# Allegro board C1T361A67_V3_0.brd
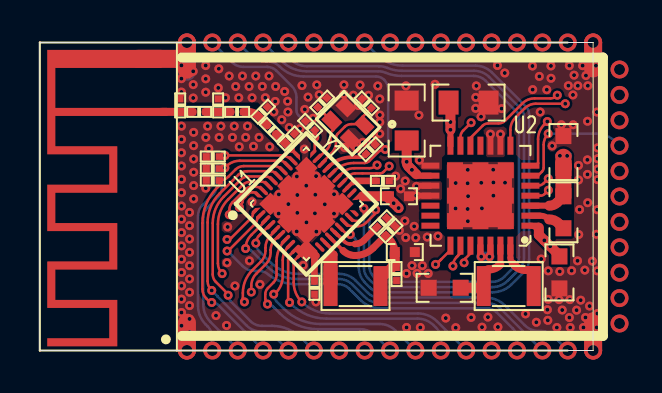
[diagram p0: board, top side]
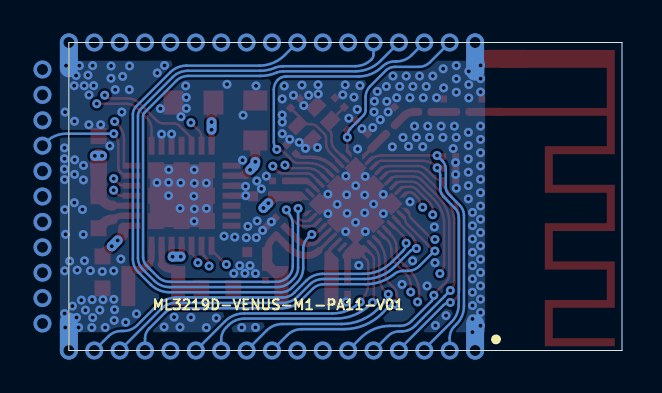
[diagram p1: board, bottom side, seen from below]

Outline 27.67 x 15.4 mm; copper layers: TOP, GND, POWER, BOTTOM. Coordinates in mm from the lower left corner of the outline.
Outline path: 0,15.4 27.67,15.4 27.67,0 26.4,0 0,0 0,15.4

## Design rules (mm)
constraint set DEFAULT: min track width 0.127, pair gap 0.1

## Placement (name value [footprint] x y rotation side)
C1  0R  [0201]  7.96 11.93 180 top
C2  NC  [0201]  11.15 11.94 45 top
C3  NC  [0201]  8.91 12.25 90 top
C4  NC  [0201]  7.01 12.25 270 top
C5  1uF  [0201]  13.51 11.24 315 top
C6  1uF  [0201]  16.54 10.06 45 top
C7  10uF  [0402]  17.95 7.71 0 top
C8  1uF  [0201]  17.15 8.48 0 top
C10  NC  [0201]  14.12 12.4 45 top
C11  NC  [0201]  16.35 12.35 315 top
C12  2.2uF  [0201]  13.73 3.14 90 top
C13  1uF  [0201]  17.1 6.41 45 top
C14  2.2uF  [0201]  17.83 3.82 270 top
C16  10uF  [0603C]  26.19 9.92 90 top
C17  100uF  [0805C]  18.34 11.5 270 top
C18  10uF  [0805C]  21.44 12.4 180 top
C19  10uF  [0603C]  20.24 3.14 180 top
C20  22uF  [0603C]  25.99 3.91 270 top
C21  NC/3.9pF  [0201]  8.64 8.5 0 top
C22  NC/3.9pF  [0201]  8.64 9.1 0 top
C23  NC/3.9pF  [0201]  8.64 9.7 180 top
C24  10uF  [0402]  18.25 4.92 0 top
C25  0.1uF  [0201]  17.53 5.99 45 top
D1  TT0321SB/NC  [0201]  12.49 10.6 225 top
L1  220pF  [0201]  11.59 11.04 135 top
L2  0R  [0201]  9.86 11.93 180 top
L3  6.8uH  [1008L]  15.78 3.22 180 top
L5  10uH  [0603L]  26.18 6.91 270 top
L6  10uH  [1008L]  23.45 3.22 180 top
U1  TL3219D  [QFN_4X4_38PIN_0P35_2P9X2P9]  13.32 7.33 45 top
U2  AEM10941  [QFN_5X5_28PIN_0P5_3P15X3P15]  22.03 7.74 180 top
U3  MODULE_15p4mm  [MODULE_BUTEO_EH_1107]  15.61 8.97 0 top
Y1  24MHz-12pF-+/-10ppm  [OSCCC160X200X065]  15.45 11.41 135 top

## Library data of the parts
C1-C4 C10 C11 = C1608_NC: User Part Number: pn; Tolerance: RichardLC
C5 C6 C8 C12-C14 C21-C23 C25 = C1005X5R1C104K: User Part Number: pn; Tolerance: RichardLC
C7 C16-C20 C24 = C1005X5R1C104K
D1 = DIODE SCHOTTKY_0: User Part Number: pn; Tolerance: RichardLC
L1 L2 L6 = MLK1608_000R: User Part Number: pn; Tolerance: RichardLC
L3 = IND_0: User Part Number: pn; Tolerance: RichardLC
L5 = MLK1608_000R
U1 = TL3219D: Tolerance: RichardLC
U2 = TLSR9517C_3
U3 = TLSR8868ET48_12: User Part Number: PN
Y1 = CRYSTAL4/SM_0

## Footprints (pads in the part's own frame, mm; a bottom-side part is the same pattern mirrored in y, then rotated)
0201
  rect 0.35x0.33 smd: 1(-0.325,0) 2(0.325,0)
0402
  rect 0.5x0.5 smd: 1(-0.5,0) 2(0.5,0)
0603C
  rect 0.8x0.8 smd: 1(-0.8,0) 2(0.8,0)
0603L
  rect 0.8x0.8 smd: 1(-0.8,0) 2(0.8,0)
0805C
  rect 1x1.2 smd: 1(-1,0) 2(1,0)
1008L
  rect 0.7x2 smd: 1(-1.25,0) 2(1.25,0)
MODULE_BUTEO_EH_1107
  rect 0.25x0.25 smd: 1(-8.255,-8.97) 2(-6.985,-8.97) 3(-5.715,-8.97) 4(-4.445,-8.97) 5(-3.175,-8.97) 6(-1.905,-8.97) 7(-0.635,-8.97) 8(0.635,-8.97) 9(1.905,-8.97) 10(3.175,-8.97) 11(4.445,-8.97) 12(5.715,-8.97) 13(6.985,-8.97) 14(8.255,-8.97) 15(9.525,-8.97) 16(10.795,-8.97) 17(12.065,-8.97) 18(13.385,-7.62) 19(13.385,-6.35) 20(13.385,-5.08) 21(13.385,-3.81) 22(13.385,-2.54) 23(13.385,-1.27) 24(13.385,0) 25(13.385,1.27) 26(13.385,2.54) 27(13.385,3.81) 28(13.385,5.08) 29(12.065,6.43) 30(10.795,6.43) 31(9.525,6.43) 32(8.255,6.43) 33(6.985,6.43) 34(5.715,6.43) 35(4.445,6.43) 36(3.175,6.43) 37(1.905,6.43) 38(0.635,6.43) 39(-0.635,6.43) 40(-1.905,6.43) 41(-3.175,6.43) 42(-4.445,6.43) 43(-5.715,6.43) 44(-6.985,6.43) 45(-8.255,6.43)
  rect 0.8x0.8 smd rot 45: 46(-2.281,0.155) 47(-3.179,-0.744) 48(-4.077,-1.641) 49(-1.383,-0.744) 50(-2.281,-1.641) 51(-3.179,-2.539) 52(-0.485,-1.641) 53(-1.383,-2.539)
  custom 0.2x0.2 smd rot 45: 54(-2.281,-4.003)
  rect 0.8x0.8 smd: 55(5.157,0.041) 56(6.427,0.041) 57(7.697,0.041) 58(5.157,-1.229) 59(6.427,-1.229) 60(7.697,-1.229) 61(5.157,-2.499) 62(6.427,-2.499) 63(7.697,-2.499)
OSCCC160X200X065
  rect 0.85x0.6 smd: 1(-0.65,-0.45) 4(-0.65,0.55)
  rect 0.85x0.65 smd: 2(0.65,-0.45) 3(0.65,0.55)
QFN_4X4_38PIN_0P35_2P9X2P9
  custom 0.045x0.045 smd: 1(-2,1.575) 10(-2,-1.575) 11(-1.4,-2) 19(1.4,-2) 20(2,-1.575) 29(2,1.575) 30(1.4,2) 38(-1.4,2)
  oval 0.6x0.18 smd: 2(-2,1.225) 3(-2,0.875) 4(-2,0.525) 5(-2,0.175) 6(-2,-0.175) 7(-2,-0.525) 8(-2,-0.875) 9(-2,-1.225) 21(2,-1.225) 22(2,-0.875) 23(2,-0.525) 24(2,-0.175) 25(2,0.175) 26(2,0.525) 27(2,0.875) 28(2,1.225)
  oval 0.18x0.6 smd: 12(-1.05,-2) 13(-0.7,-2) 14(-0.35,-2) 15(0,-2) 16(0.35,-2) 17(0.7,-2) 18(1.05,-2) 31(1.05,2) 32(0.7,2) 33(0.35,2) 34(0,2) 35(-0.35,2) 36(-0.7,2) 37(-1.05,2)
  custom 0.725x0.725 smd: 39(0,0)
QFN_5X5_28PIN_0P5_3P15X3P15
  rect 0.9x0.3 smd: 1(-2.5,1.5) 2(-2.5,1) 3(-2.5,0.5) 4(-2.5,0) 5(-2.5,-0.5) 6(-2.5,-1) 7(-2.5,-1.5) 15(2.5,-1.5) 16(2.5,-1) 17(2.5,-0.5) 18(2.5,0) 19(2.5,0.5) 20(2.5,1) 21(2.5,1.5)
  rect 0.3x0.9 smd: 8(-1.5,-2.5) 9(-1,-2.5) 10(-0.5,-2.5) 11(0,-2.5) 12(0.5,-2.5) 13(1,-2.5) 14(1.5,-2.5) 22(1.5,2.5) 23(1,2.5) 24(0.5,2.5) 25(0,2.5) 26(-0.5,2.5) 27(-1,2.5) 28(-1.5,2.5)
  rect 3.15x3.15 smd: 29(0,0)

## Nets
GND: C1.2 C2.2 C3.2 C4.1 C4.2 C5.1 C6.2 C7.2 C8.2 C10.2 C11.1 C12.1 C13.2 C14.2 C16.2 C17.1 C18.1 C19.2 C20.2 C21.1 C22.1 C23.2 C24.2 C25.2 D1.1 U1.39 U2.9 U2.10 U2.15 U2.17 U2.18 U2.29 U3.1 U3.17 U3.29 U3.45 U3.46 U3.47 U3.48 U3.49 U3.50 U3.51 U3.52 U3.53 U3.54 U3.55 U3.56 U3.57 U3.58 U3.59 U3.60 U3.61 U3.62 U3.63 Y1.2 Y1.4
AEM_BATT: C17.2 U2.16 U3.37
AEM_BOOST: C20.1 U2.1 U3.21
AEM_BUCK: C16.1 L5.1 U2.3 U3.26
AEM_CFG0: U2.6 U3.25
AEM_CFG1: U2.5 U3.24
AEM_CFG2: U2.4 U3.23
AEM_CHRDY: U2.23 U3.19
AEM_ENHV: U2.12 U3.30
AEM_FBHV: U2.13 U3.34
AEM_HVOUT: C18.2 U2.14 U3.35
AEM_OVCH: U2.22 U3.18
AEM_OVDIS: U2.24 U3.20
AEM_SELMPP0: U2.8 U3.28
AEM_SELMPP1: U2.7 U3.27
AEM_SRC: U2.25 U2.26 U3.22
TL_ANT: D1.2(CATHODE) L1.1 U1.30
TL_AVDD1P25: C14.1 C24.1 C25.1 L3.1 U1.14
TL_AVDD3: C8.1 U1.22
TL_PA0: U1.37 U3.32
TL_PA1: U1.7 U3.9(PIN9)
TL_PA2: U1.8 U3.10
TL_PA3: U1.10 U3.12
TL_PA4: U1.9 U3.11
TL_PA5_DM: U1.6 U3.8
TL_PA6_DP: U1.5 U3.7
TL_PA7_SWS: U1.36 U3.13
TL_PB0: U1.1 U3.31
TL_PB1: U1.38 U3.33
TL_PB5: U1.18 U3.41
TL_PB6: U1.17 U3.42
TL_PB7: U1.16 U3.38
TL_PC0_AMICP: U1.23 U3.40
TL_PC1_AMICN: U1.24 U3.39
TL_PC2: U1.25 U3.43
TL_PD1: U1.2 U3.14
TL_PD4: U1.3 U3.15
TL_PD6: U1.4 U3.16
TL_PE2: C21.2 U1.33 U3.4
TL_PE4: C23.1 U1.31 U3.2
TL_PE5: C22.2 U1.32 U3.3
TL_PE6: U1.35 U3.6
TL_PE7: U1.34 U3.5
TL_RESET: C5.2 U1.29 U3.44
TL_VBAT: C7.1 U1.20 U3.36
TL_XC1: C10.1 U1.28 Y1.3
TL_XC2: C11.2 U1.27(XC2) Y1.1
N20473879: C2.1 L1.2 L2.1
N20475567: C19.1 L6.2 U2.27
N20475608: L6.1 U2.28
N20475681: L5.2 U2.2(SWBUCK)
N20493055: C1.1 C3.1 L2.2
N20502827: C6.1 U1.26
N20503268: C12.2 U1.11
N20503276: C13.1 U1.15
N20503917: L3.2 U1.13

Pads without a net: U1 12 19 21; U2 11 19 20 21

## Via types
v1: diameter 0.45, hole 0.2, TOP to BOTTOM, 286 vias
v2: diameter 0.9, hole 0.55, TOP to BOTTOM, 45 vias

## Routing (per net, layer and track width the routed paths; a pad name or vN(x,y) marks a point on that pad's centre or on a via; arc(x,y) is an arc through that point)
GND: length 29.8
  TOP w0.127: U2.10 v1(22.53,10.82) ; C18.1 22.06,12.4 v1(21.8,12.66) ; U2.9 v1(23.03,10.82)
  TOP w0.3: U2.18 v1(18.82,7.74) ; 18.98,8.24 U2.17
  TOP w0.4: 6.07,11.93 C4.2 C1.2
  TOP w0.9: v2(7.35,0) 7.35,1.39 ; 4.88,14.58 7.33,14.58 ; v2(27.67,15.4) 27.67,14.11 ; 27.67,1.46 v2(27.67,0) ; v2(7.35,15.4) 7.35,14.04
  GND w0.9: 27.67,13.99 v2(27.67,15.4) ; v2(7.35,0) 7.35,1.37 ; v2(7.35,15.4) 7.35,13.93 ; 27.67,1.77 v2(27.67,0)
  POWER w0.9: v2(7.35,15.4) 7.35,14.12 ; v2(7.35,0) 7.35,1.47 ; v2(27.67,15.4) 27.67,14.03 ; 27.67,1.47 v2(27.67,0)
  BOTTOM w0.9: v2(27.67,15.4) 27.67,14.11 ; v2(7.35,15.4) 7.35,13.94 ; v2(7.35,0) 7.35,1.34 ; v2(27.67,0) 27.67,1.44
  vias: v1(7.07,14.26) v1(7.07,13.59) v1(7.07,12.92) v1(7.08,11.22) v1(7.08,10.56) v1(7.08,9.89) v1(7.08,9.23) v1(7.08,8.56) v1(7.08,7.89) v1(7.08,7.23) v1(7.08,6.56) v1(7.08,5.9) v1(7.08,5.23) v1(7.08,4.56) v1(7.08,3.9) v1(7.08,3.23) v1(7.08,2.57) v1(7.08,1.9) v1(7.08,1.24) v1(7.48,6.9) v1(7.48,6.24) v1(7.48,5.57) v1(7.48,4.91) v1(7.48,4.24) v1(7.48,3.58) v1(7.48,2.91) v1(7.48,2.25) v1(7.48,1.58) v1(7.48,0.92) v1(7.67,13.96) v1(7.67,13.29) v1(7.67,12.63) v1(7.69,10.91) v1(7.69,10.24) v1(7.69,9.57) v1(7.69,8.91) v1(7.69,8.25) v1(7.69,7.58) v1(8.29,14.25) v1(8.29,13.58) v1(8.29,12.91) v1(8.3,10.65) v1(8.29,8.12) v1(8.39,11.22) v1(8.33,9.4) v1(8.32,8.8) v1(8.45,10.1) v1(8.8,1.75) v1(8.95,14.09) v1(8.92,13.13) v1(8.96,10.65) v1(9.05,11.22) v1(9.28,12.64) v1(9.39,6.18) v1(9.36,4.39) v1(9.33,1.25) v1(9.46,13.72) v1(9.63,10.66) v1(9.79,13.2) v1(9.72,11.22) v1(9.75,3.23) v1(9.94,12.64) v1(9.97,10.19) v1(10.13,13.72) v1(10.29,10.66) v1(10.38,11.22) v1(10.46,13.2) v1(10.48,4.49) v1(10.61,12.64) v1(10.68,10.21) v1(10.61,7.44) v1(10.8,13.72) v1(10.96,10.66) v1(11,3.31) v1(11.12,13.2) v1(11.27,12.64) v1(11.46,13.72) v1(11.49,10.18) v1(11.79,13.2) v1(11.77,12.45) v1(11.7,11.93) v1(11.95,7.8) v1(11.94,6.85) v1(12.09,11.54) v1(12.24,12.95) v1(12.39,12.46) v1(12.4,11.93) v1(12.47,11.15) v1(12.43,7.32) v1(12.85,8.7) v1(12.87,7.77) v1(12.87,6.88) v1(12.84,5.95) v1(13.01,11.09) v1(13.11,13.25) v1(13.17,4.26) v1(13.25,12.06) v1(13.23,10.07) v1(13.32,8.24) v1(13.33,6.41) v1(13.41,12.67) v1(13.66,11.61) v1(13.77,7.79) v1(13.75,6.86) v1(13.85,13.28) v1(13.81,8.72) v1(13.82,5.95) v1(13.8,2.43) v1(13.97,12.79) v1(14.25,7.31) v1(14.71,7.81) v1(14.71,6.84) v1(15.2,12.82) v1(15.21,13.29) v1(15.24,10.15) v1(15.67,12.77) v1(15.84,10.11) v1(15.92,12.25) v1(16.01,13.27) v1(16.15,10.41) v1(16.44,12.76) v1(16.62,10.56) v1(16.9,13.23) v1(17,12.58) v1(17,11.42) v1(17,10.84) v1(17,11.78) v1(17.54,6.44) v1(17.79,8.72) v1(17.98,6) v1(18.04,8.08) v1(18.27,8.48) v1(18.25,6.48) v1(18.3,5.64) v1(18.31,13.23) v1(18.34,3.85) v1(18.34,1.15) v1(18.61,4.25) v1(18.72,6.21) v1(18.8,5.64) v1(18.83,8.21) v1(18.86,3.86) v1(18.96,11.76) v1(18.98,9.52) v1(19.02,1.15) v1(19.12,4.24) v1(19.37,5.67) v1(19.42,3.85) v1(19.76,13.31) v1(19.91,5.72) v1(20.3,1.62) v1(20.8,8.37) v1(20.79,7.1) v1(20.8,1.14) v1(21.4,9.03) v1(21.39,8.36) v1(21.39,7.08) v1(21.41,7.71) v1(21.4,6.46) v1(21.57,1.65) v1(21.8,12.11) v1(21.83,13.23) v1(22.06,11.69) v1(22.07,8.38) v1(22.11,7.11) v1(22.11,1.17) v1(22.41,1.67) v1(22.67,9.04) v1(22.68,8.4) v1(22.68,7.74) v1(22.88,14.25) v1(22.91,1.18) v1(23.09,12.09) v1(23.25,13.88) v1(23.26,8.39) v1(24.29,1.83) v1(24.64,14.22) v1(24.65,13.04) v1(24.83,1.41) v1(24.98,13.7) v1(25.02,11.92) v1(25.07,4.57) v1(25.35,13.04) v1(25.38,2.04) v1(25.42,3.98) v1(25.42,2.56) v1(25.4,1.51) v1(25.56,14.23) v1(25.56,13.61) v1(25.62,10.23) v1(25.86,1.15) v1(25.96,2.54) v1(26.08,11.29) v1(26,3.95) v1(26.12,2.02) v1(26.48,14.24) v1(26.43,13.24) v1(26.48,1.65) v1(26.59,3.99) v1(26.51,2.54) v1(26.52,1.15) v1(26.66,12.78) v1(26.67,11.29) v1(26.72,13.77) v1(26.89,4.48) v1(26.84,2.02) v1(26.91,13.24) v1(26.94,9.25) v1(26.94,8.53) v1(26.99,7.05) v1(26.95,5.8) v1(27.05,2.52) v1(27.14,14.24) v1(27.19,1.15) v1(27.25,4.02) v1(27.29,1.65) v1(27.31,13.75) v1(27.39,11.46) v1(27.38,9.53) v1(27.39,8.81) v1(27.4,7.39) v1(27.41,13.24) v1(27.49,2.22) v1(27.63,4.47) v1(27.81,14.24) v1(27.86,11.92) v1(27.89,10.13) v1(27.89,9.59) v1(27.89,9.07) v1(27.89,8.54) v1(27.87,7.04) v1(27.84,5.81) v1(27.88,3.98) v1(27.89,1.85) v1(27.85,1.15)
AEM_BATT: length 9.8
  TOP w0.3: U2.16 19,8.74 arc(18.9,8.76) 18.82,8.81
  TOP w0.5: 18.82,8.81 v1(18.61,9.03) 18.44,9.19 arc(18.37,9.3) v1(18.34,9.44) C17.2
  POWER w0.5: v1(18.61,9.03) 18.44,9.19 arc(18.37,9.3) v1(18.34,9.44) arc(18.34,9.44) 18.34,9.45 18.34,11.85 arc(18.26,12.22) 18.06,12.52 18.06,12.52 arc(17.65,13.13) 17.51,13.85 v2(17.51,15.4)
  BOTTOM w0.5: v1(18.61,9.03) 18.44,9.19 arc(18.37,9.3) v1(18.34,9.44)
AEM_BOOST: length 7
  TOP w0.127: U2.1 24.86,6.24 24.96,6.14
  TOP w0.3: 24.89,6.09 arc(24.72,6.2) U2.1
  TOP w0.5: 24.96,6.14 24.96,5.78 v1(25.23,5.5) 25.23,5.5 v1(25.52,5.21) 25.99,4.75 C20.1
  POWER w0.5: v2(28.99,5.16) 25.65,5.16 arc(25.58,5.17) v1(25.52,5.21) arc(25.52,5.21) 25.52,5.22 v1(25.23,5.5)
  BOTTOM w0.5: v1(25.23,5.5) 25.52,5.22 arc(25.52,5.21) v1(25.52,5.21)
AEM_BUCK: length 8.8
  TOP w0.127: 26.19,9.29 arc(26.23,9.53) v1(26.37,9.73) ; v1(26.01,9.74) arc(26.14,9.54) 26.19,9.31
  TOP w0.3: U2.3 25.48,7.24
  TOP w0.5: L5.1 26.18,7.71 25.87,7.4 arc(25.69,7.28) 25.48,7.24
  TOP w0.8: L5.1 26.18,9.12 arc(26.18,9.12) C16.1 26.19,9.69
  POWER w0.5: v1(26.01,9.74) 26.36,9.74 v1(26.37,9.73) arc(26.62,9.78) 26.83,9.92 28.05,11.14 arc(28.24,11.27) 28.46,11.31 28.51,11.31 arc(28.77,11.36) v2(28.99,11.51)
  BOTTOM w0.5: v1(26.01,9.74) 26.36,9.74 arc(26.36,9.74) v1(26.37,9.73)
AEM_CFG0: length 6.6
  TOP w0.127: U2.6 24.91,8.74 25.11,8.94 arc(25.17,9.03) 25.19,9.15 25.19,10.29 arc(25.25,10.59) v1(25.42,10.84)
  BOTTOM w0.127: v1(25.42,10.84) 27.82,10.84 arc(28.35,10.73) 28.8,10.43 v2(28.99,10.24) 28.86,10.37
AEM_CFG1: length 5.1
  TOP w0.127: U2.5 24.9,8.24 arc(25.06,8.27) 25.2,8.37 v1(25.43,8.59)
  POWER w0.127: v2(28.99,8.97) 28.35,8.33 arc(28.08,8.15) 27.77,8.09 26.38,8.09 arc(26.05,8.15) 25.78,8.34 25.6,8.52 arc(25.52,8.57) v1(25.43,8.59)
AEM_CFG2: length 4.6
  TOP w0.127: v1(25.43,8.01) 25.24,7.82 arc(25.15,7.76) 25.04,7.74 U2.4
  POWER w0.127: v2(28.99,7.7) arc(28.85,7.79) 28.69,7.82 25.89,7.82 arc(25.64,7.87) v1(25.43,8.01)
AEM_CHRDY: length 10.2
  TOP w0.127: U2.23 21.03,4.86 20.91,4.73 ; 20.91,4.73 20.87,4.7 ; 20.91,4.73 20.84,4.67 arc(20.7,4.46) v1(20.66,4.22) 20.66,4.26
  POWER w0.127: v2(28.99,2.62) 28.56,3.05 arc(28.35,3.19) 28.11,3.24 22.23,3.24 arc(21.56,3.37) 21,3.75 20.75,3.99 arc(20.68,4.1) v1(20.66,4.22)
AEM_ENHV: length 8.3
  TOP w0.127: v1(25.88,12.77) 25.84,12.73 arc(25.7,12.64) 25.54,12.61 24.74,12.61 arc(24.41,12.54) 24.13,12.35 23.27,11.49 arc(23.12,11.39) 22.94,11.35 22.42,11.35 arc(22.27,11.33) 22.14,11.24 21.53,10.63 U2.12
  POWER w0.127: v2(26.4,15.4) 26.08,15.08 arc(26.01,14.98) 25.99,14.85 25.99,13.03 arc(25.96,12.89) v1(25.88,12.77)
AEM_FBHV: length 5.4
  TOP w0.127: U2.13 21.03,10.67 arc(21.07,10.84) 21.17,10.99 v1(21.57,11.39)
  POWER w0.127: v1(21.57,11.39) arc(21.43,11.6) 21.38,11.84 21.38,15.26 arc(21.36,15.33) v2(21.32,15.4)
AEM_HVOUT: length 7.1
  TOP w0.3: v1(20.53,11.04) U2.14
  TOP w0.5: C18.2 20.53,12.3 v1(20.53,11.42) v1(20.53,11.04)
  POWER w0.5: v1(20.53,11.04) v1(20.53,11.42) 20.53,11.42 20.53,13.22 arc(20.48,13.5) 20.32,13.75 arc(20.12,14.04) 20.05,14.39 v2(20.05,15.4) 20.05,15.4
  BOTTOM w0.5: v1(20.53,11.04) v1(20.53,11.42)
AEM_OVCH: length 11.9
  TOP w0.127: 20.06,4.55 19.83,4.32 arc(19.81,4.31) v1(19.79,4.3) ; 20.06,4.55 20.53,5.02 U2.22 ; 20.06,4.55 19.84,4.32
  POWER w0.127: v1(19.79,4.3) 19.84,4.3 arc(19.95,4.28) 20.05,4.21 20.7,3.57 arc(21.35,3.13) 22.12,2.98 26.99,2.98 arc(27.33,2.91) 27.62,2.72 v2(28.99,1.35)
AEM_OVDIS: length 9.4
  TOP w0.127: v1(21.21,4.39) 21.21,4.43 arc(21.23,4.53) 21.29,4.61 21.53,4.85 U2.24
  POWER w0.127: v2(28.99,3.89) 28.69,3.59 arc(28.59,3.53) 28.48,3.5 22.18,3.5 arc(21.8,3.58) 21.47,3.8 21.45,3.82 arc(21.28,4.08) v1(21.21,4.39)
AEM_SELMPP0: length 7.6
  TOP w0.127: U2.8 23.53,11.04 arc(23.6,11.37) 23.78,11.65 24.25,12.11 arc(24.5,12.28) 24.8,12.34 v1(26.28,12.34)
  POWER w0.127: v1(26.28,12.34) 26.93,12.34 arc(27.17,12.39) 27.38,12.52 28.85,13.99 arc(28.91,14.03) v2(28.99,14.05)
AEM_SELMPP1: length 6.7
  TOP w0.127: v1(25.38,11.45) 25.21,11.28 arc(24.99,10.96) 24.92,10.57 24.92,9.37 24.79,9.24 U2.7
  POWER w0.127: v2(28.99,12.78) 28.39,12.78 arc(28.05,12.71) 27.76,12.52 27.55,12.31 arc(27.11,12.02) 26.6,11.91 26.34,11.91 arc(25.88,11.82) 25.49,11.56 v1(25.38,11.45)
AEM_SRC: length 9.1
  TOP w0.3: v1(22.07,4.69) 22.03,4.73 U2.25 ; U2.26 22.53,4.74 v1(22.48,4.69)
  POWER w0.5: v1(22.07,4.69) 22.47,4.69 arc(22.48,4.69) v1(22.48,4.69) arc(22.7,4.73) 22.89,4.86 23.97,5.94 arc(24.52,6.3) 25.16,6.43 v2(28.99,6.43)
  BOTTOM w0.5: v1(22.07,4.69) 22.47,4.69 arc(22.48,4.69) v1(22.48,4.69)
TL_ANT: length 1.5
  TOP w0.18: 12.55,10.09 12.9,9.73 U1.30
  TOP w0.4: 12.55,10.09 D1.2 L1.1
TL_AVDD1P25: length 7.5
  TOP w0.18: U1.14 15.15,5 arc(15.16,5) 15.16,5
  TOP w0.2: C24.1 17.83,4.84 C14.1 17.6,4.15
  TOP w0.35: 15.16,5 arc(15.43,4.82) 15.76,4.75 arc(16.25,4.85) 16.67,5.13 C25.1 17.47,5.59 arc(17.68,5.28) C24.1
  TOP w0.5: L3.1 17.03,3.58 17.75,4.29 C24.1
TL_AVDD3: length 1.8
  TOP w0.18: 15.79,8.48 15.66,8.35 15.59,8.35 ; 15.59,8.35 15.72,8.49 ; 15.59,8.35 U1.22
  TOP w0.33: 15.79,8.48 C8.1
TL_PA0: length 26.1
  TOP w0.127: U1.37 11.11,8.06 arc(10.97,8.15) 10.8,8.19 10.58,8.19 arc(10.42,8.15) 10.28,8.06 9.63,7.41 arc(9.51,7.23) 9.47,7.02 v1(9.47,6.79)
  POWER w0.127: v2(23.86,15.4) 23.94,15.32 23.94,8.23 arc(23.88,7.92) 23.71,7.66 22.4,6.35 arc(20.83,5.3) 18.97,4.93 13.58,4.93 arc(12.94,5.06) 12.39,5.42 11.8,6.01 arc(11.44,6.25) 11.02,6.34 10.56,6.34 arc(9.97,6.46) v1(9.47,6.79)
TL_PA1: length 10.5
  TOP w0.127: U1.7 12.28,5.54 arc(11.95,5.05) 11.83,4.46 11.83,3.76 arc(11.79,3.57) 11.69,3.41 11.4,3.12 arc(11.3,2.98) 11.27,2.81 11.27,2.59 arc(11.3,2.44) v1(11.38,2.32)
  BOTTOM w0.127: v2(17.51,0) 16.74,0.77 arc(16.41,0.99) 16.02,1.07 13.91,1.07 arc(12.87,1.27) 12,1.86 11.65,2.21 arc(11.52,2.29) v1(11.38,2.32)
TL_PA2: length 11
  TOP w0.127: U1.8 12.42,5.19 arc(12.22,4.88) 12.14,4.52 12.14,3.72 arc(12.05,3.27) 11.8,2.89 11.73,2.82 v1(11.69,2.82)
  BOTTOM w0.127: v2(18.78,0) 17.78,1 arc(17.42,1.24) 16.99,1.32 14.03,1.32 arc(13.04,1.52) 12.21,2.08 11.85,2.44 arc(11.73,2.61) v1(11.69,2.82)
TL_PA3: length 11.7
  TOP w0.127: 13.07,2.46 v1(13.1,2.43) arc(12.8,2.88) 12.69,3.41 12.69,4.31 arc(12.72,4.46) 12.8,4.58 U1.10
  BOTTOM w0.127: v2(21.32,0) 19.87,1.45 arc(19.42,1.75) 18.9,1.85 14.49,1.85 arc(13.73,2) v1(13.1,2.43)
TL_PA4: length 11.7
  TOP w0.127: U1.9 12.52,4.79 arc(12.44,4.67) 12.41,4.53 12.41,2.58 arc(12.43,2.48) v1(12.48,2.4)
  BOTTOM w0.127: v1(12.48,2.4) 12.57,2.32 arc(13.37,1.78) 14.32,1.6 18.88,1.6 arc(19.32,1.51) 19.69,1.26 19.8,1.15 arc(19.99,0.87) 20.05,0.55 v2(20.05,0)
TL_PA5_DM: length 10.5
  TOP w0.127: U1.6 12,5.79 11.76,5.56 arc(11.6,5.31) 11.54,5.02 11.54,4.91 arc(11.47,4.58) 11.29,4.31 10.82,3.84 arc(10.64,3.56) 10.57,3.23 v1(10.57,2.92)
  POWER w0.127: v2(16.24,0) 15.49,0.75 arc(14.55,1.38) 13.45,1.6 11.46,1.6 arc(11.12,1.66) 10.83,1.85 arc(10.71,2.03) 10.67,2.24 10.67,2.67 arc(10.65,2.81) v1(10.57,2.92)
TL_PA6_DP: length 10.3
  TOP w0.127: U1.5 11.79,6 11.54,5.75 arc(11.35,5.47) 11.28,5.13 11.28,4.99 arc(11.22,4.7) 11.06,4.45 10.62,4.01 arc(10.27,3.49) 10.15,2.88 10.15,2.62 arc(10.17,2.52) v1(10.23,2.43)
  POWER w0.127: v2(14.97,0) 14.97,0.52 arc(14.94,0.66) 14.86,0.78 arc(14.25,1.19) 13.53,1.33 11.49,1.33 arc(10.97,1.44) 10.53,1.73 10.5,1.76 arc(10.3,2.07) v1(10.23,2.43)
TL_PA7_SWS: length 21.1
  TOP w0.127: 11.42,8.25 11.33,8.33 arc(11.21,8.41) 11.07,8.44 10.55,8.44 arc(10.32,8.4) 10.13,8.27 9.41,7.55 arc(9.03,6.99) 8.9,6.32 8.9,4.35 arc(8.96,4.08) v1(9.11,3.85)
  POWER w0.127: v1(9.11,3.85) 9.12,3.84 arc(9.23,3.76) 9.36,3.74 15.86,3.74 arc(18.57,3.2) 20.87,1.66 22.53,0 v2(22.59,0)
TL_PB0: length 26.6
  TOP w0.127: U1.1 10.8,6.99 10.65,6.85 10.65,6.85 arc(10.63,6.72) 10.56,6.62 9.59,5.65 arc(9.48,5.58) v1(9.36,5.55)
  POWER w0.127: v1(9.36,5.55) 9.66,5.86 arc(9.91,6.02) 10.2,6.08 11,6.08 arc(11.35,6.01) 11.64,5.81 12.25,5.21 arc(12.84,4.81) 13.54,4.68 18.95,4.68 arc(20.98,5.08) 22.7,6.23 23.84,7.36 arc(24.11,7.77) 24.2,8.24 24.2,14.14 arc(24.25,14.39) 24.39,14.6 25.13,15.34 v2(25.13,15.4)
TL_PB1: length 24.5
  TOP w0.127: U1.38 10.82,7.85 arc(10.75,7.9) 10.67,7.91 10.61,7.91 arc(10.51,7.89) 10.42,7.83 10.4,7.82 10.29,7.7 10.21,7.63 arc(10.15,7.53) 10.12,7.41 arc(10.07,7.28) 9.98,7.17 v1(9.97,7.16)
  POWER w0.127: v2(22.59,15.4) 23.48,14.51 arc(23.63,14.29) 23.68,14.03 23.68,8.32 arc(23.63,8.04) 23.47,7.81 22.18,6.51 arc(20.72,5.54) 19,5.2 13.54,5.2 arc(13.03,5.3) 12.6,5.58 12,6.18 arc(11.55,6.49) 11.01,6.59 arc(10.58,6.68) 10.21,6.93 v1(9.97,7.16)
TL_PB5: length 34.3
  TOP w0.127: 15.48,6.66 U1.18 15.54,6.6 arc(15.68,6.5) 15.85,6.47 15.88,6.47 arc(16.02,6.5) 16.14,6.58 arc(16.19,6.65) 16.2,6.73 v1(16.2,7.1)
  BOTTOM w0.127: v2(12.43,15.4) 12.43,14.8 arc(12.46,14.67) 12.53,14.55 arc(12.91,14.3) 13.35,14.22 16.95,14.22 ; v1(16.2,7.1) 16.2,4.14 arc(16.26,3.84) 16.44,3.58 16.56,3.46 arc(16.88,3.25) 17.26,3.17 22.63,3.17 arc(23.05,3.25) 23.4,3.49 23.99,4.08 arc(24.16,4.33) 24.21,4.62 24.21,11.73 arc(24.18,11.92) 24.07,12.07 22.47,13.68 arc(22.13,13.9) 21.73,13.98 18.11,13.98 arc(17.74,14.02) 17.37,14.13 arc(17.16,14.19) 16.95,14.22 ; 16.95,14.22 16.95,14.22
TL_PB6: length 34.7
  TOP w0.127: U1.17 15.28,6.36 arc(15.44,6.25) 15.63,6.21 15.9,6.21 arc(16.12,6.26) 16.31,6.39 16.72,6.8 arc(16.78,6.88) 16.8,6.97 16.8,7.03 v1(16.79,7.03)
  BOTTOM w0.127: v2(11.16,15.4) 12.08,14.48 arc(12.66,14.09) 13.34,13.96 16.93,13.96 arc(17.12,13.94) 17.3,13.89 arc(17.68,13.77) 18.09,13.73 21.7,13.73 arc(22.02,13.66) 22.3,13.48 23.89,11.89 arc(23.94,11.81) 23.96,11.72 23.96,4.66 arc(23.91,4.44) 23.79,4.25 23.23,3.69 arc(22.95,3.5) 22.61,3.43 17.3,3.43 arc(16.98,3.5) 16.7,3.68 arc(16.53,3.94) 16.47,4.24 16.47,6.26 arc(16.54,6.65) 16.76,6.97 16.79,7 v1(16.79,7.03)
TL_PB7: length 29.4
  TOP w0.127: U1.16 15.22,5.93 arc(15.36,5.83) v1(15.52,5.8)
  BOTTOM w0.127: v2(16.24,15.4) 16.87,14.77 arc(17.45,14.38) 18.14,14.24 21.79,14.24 arc(22.23,14.15) 22.6,13.91 24.31,12.2 arc(24.43,12.02) 24.47,11.81 24.47,4.57 arc(24.4,4.22) 24.2,3.92 23.58,3.3 arc(23.15,3.01) 22.64,2.91 17.04,2.91 arc(16.76,2.97) 16.52,3.13 16.26,3.39 arc(16.03,3.74) 15.95,4.14 15.95,5.07 arc(15.89,5.38) 15.71,5.65 15.55,5.8 v1(15.52,5.8)
TL_PC0_AMICP: length 12
  TOP w0.127: U1.23 15.48,8.74 arc(15.6,8.82) 15.75,8.85 16.12,8.85 ; 16.83,8.85 17.01,8.85 arc(17.1,8.87) 17.17,8.92 v1(17.47,9.22)
  TOP w0.128: 16.12,8.85 16.83,8.85
  POWER w0.127: v2(13.7,15.4) 14.29,14.81 arc(14.44,14.58) 14.5,14.31 14.5,10.22 arc(14.58,9.81) 14.81,9.47 15.17,9.11 arc(15.45,8.92) 15.78,8.85 16.92,8.85 arc(17.09,8.89) 17.24,8.98 v1(17.47,9.22)
TL_PC1_AMICN: length 10.2
  TOP w0.127: v1(16.86,9.27) arc(16.69,9.16) 16.48,9.12 ; 15.72,9.12 arc(15.39,9.05) 15.1,8.86
  TOP w0.128: v1(16.86,9.27) 16.86,9.25 ; 15.1,8.86 U1.24 ; 16.48,9.12 15.72,9.12
  POWER w0.127: v2(14.97,15.4) 14.76,15.19 14.76,10.27 arc(14.82,9.92) 15.02,9.63 15.33,9.32 arc(15.56,9.17) 15.82,9.11 16.48,9.11 arc(16.69,9.15) v1(16.86,9.27)
TL_PC2: length 14.6
  TOP w0.127: U1.25 14.72,8.97 arc(15.17,9.27) 15.69,9.37 ; 16.46,9.47 arc(16.36,9.4) 16.23,9.37 ; 17.28,10.05 arc(17.06,10.01) 16.88,9.88
  TOP w0.128: 16.23,9.37 15.69,9.37 ; 16.88,9.88 16.46,9.47 ; v1(17.27,10.05) 17.28,10.05
  BOTTOM w0.127: v2(9.89,15.4) 10.52,14.77 arc(10.87,14.54) 11.28,14.45 11.36,14.45 arc(11.71,14.39) 12,14.19 arc(12.54,13.83) 13.18,13.7 16.81,13.7 arc(17.03,13.66) 17.22,13.53 arc(17.37,13.31) 17.42,13.05 17.42,10.42 arc(17.38,10.22) v1(17.27,10.05)
TL_PD1: length 19.3
  TOP w0.127: U1.2 11.01,6.78 10.87,6.65 arc(10.83,6.46) 10.73,6.3 10.71,6.28 9.4,4.97 v1(9.36,4.97)
  BOTTOM w0.127: v2(23.86,0) 23.86,0.61 arc(23.81,0.87) 23.66,1.09 23.65,1.1 22.84,1.91 arc(22.62,2.06) 22.35,2.11 17.01,2.11 arc(16.49,2.22) 16.04,2.52 15.47,3.09 arc(15.22,3.26) 14.92,3.31 12.82,3.31 arc(12.1,3.43) 11.45,3.78 arc(11.22,3.93) 10.95,3.98 10.72,3.98 arc(10.41,4.04) 10.14,4.22 9.39,4.97 v1(9.36,4.97)
TL_PD4: length 18.5
  TOP w0.127: U1.3 11.29,6.5 10.58,5.79 10.56,5.77 arc(10.36,5.46) v1(10.29,5.1)
  BOTTOM w0.127: v2(25.13,0) 23.04,2.09 arc(22.72,2.3) 22.33,2.38 17,2.38 arc(16.58,2.46) 16.22,2.7 15.63,3.29 arc(15.32,3.5) 14.95,3.57 12.87,3.57 arc(12.06,3.74) 11.37,4.19 10.59,4.97 arc(10.45,5.07) v1(10.29,5.1)
TL_PD6: length 18.8
  TOP w0.127: U1.4 11.5,6.29 11.03,5.81 10.95,5.74 arc(10.84,5.57) v1(10.8,5.37)
  BOTTOM w0.127: v2(26.4,0) 25.69,0.71 arc(25.4,0.91) 25.05,0.98 24.95,0.98 arc(24.57,1.05) 24.25,1.27 23.28,2.24 arc(22.82,2.54) 22.28,2.65 16.97,2.65 arc(16.66,2.71) 16.4,2.89 15.79,3.5 arc(15.42,3.74) 14.98,3.83 12.94,3.83 arc(12.17,3.99) 11.51,4.42 11.47,4.46 11.01,4.93 10.96,4.97 arc(10.84,5.15) v1(10.8,5.37)
TL_PE2: length 13.6
  TOP w0.127: U1.33 12.09,9.06 arc(11.91,9.18) 11.69,9.22 10.19,9.22 arc(9.97,9.18) 9.79,9.06 9.42,8.68 arc(9.21,8.55) C21.2 8.97,8.3 arc(8.96,8.25) 8.93,8.21 8.86,8.14 arc(8.32,7.33) 8.13,6.36 8.13,3.07 arc(8.18,2.82) 8.32,2.6 8.47,2.45 arc(8.52,2.42) v1(8.59,2.4)
  BOTTOM w0.127: v2(11.16,0) 11.16,0.04 8.94,2.26 arc(8.78,2.36) v1(8.59,2.4)
TL_PE4: length 14.2
  TOP w0.127: C23.1 9.13,9.7 arc(9.2,9.71) v1(9.25,9.75) 9.26,9.75 12,9.75 arc(12.35,9.68) U1.31
  BOTTOM w0.127: v2(8.62,0) 8.62,0.63 arc(8.56,0.95) 8.38,1.21 8.29,1.31 arc(8.01,1.73) 7.91,2.22 7.91,6.75 arc(7.96,7.03) 8.12,7.26 8.68,7.82 arc(8.78,7.97) 8.82,8.15 8.82,9.07 arc(8.86,9.29) 8.99,9.48 v1(9.25,9.75)
TL_PE5: length 13.8
  TOP w0.127: 12.41,9.24 12.26,9.38 arc(12.15,9.46) 12.01,9.49 9.99,9.49 arc(9.63,9.41) 9.32,9.21 v1(9.25,9.14) arc(9.21,9.11) 9.16,9.1 C22.2
  BOTTOM w0.127: v2(9.89,0) 9.89,0.07 8.54,1.42 arc(8.26,1.83) 8.17,2.31 8.17,6.65 arc(8.22,6.91) 8.36,7.12 8.92,7.69 arc(9.05,7.87) 9.1,8.1 9.1,8.77 arc(9.13,8.97) v1(9.25,9.14)
TL_PE6: length 13.7
  TOP w0.127: U1.35 11.58,8.58 arc(11.44,8.67) 11.28,8.7 10.43,8.7 arc(10.22,8.66) 10.03,8.54 9.19,7.69 arc(8.78,7.08) 8.64,6.36 8.64,3.81 arc(8.68,3.6) 8.8,3.43 9.37,2.85 arc(9.4,2.81) v1(9.41,2.76)
  BOTTOM w0.127: v2(13.7,0) 13.08,0.62 arc(12.4,1.07) 11.61,1.23 11.11,1.23 arc(10.79,1.29) 10.52,1.47 9.54,2.46 arc(9.44,2.6) v1(9.41,2.76)
TL_PE7: length 13.5
  TOP w0.127: U1.34 11.8,8.85 arc(11.68,8.93) 11.53,8.96 10.35,8.96 arc(10.12,8.92) 9.93,8.79 8.99,7.85 arc(8.54,7.18) 8.38,6.39 8.38,3.47 arc(8.43,3.23) 8.57,3.02 v1(8.59,3)
  BOTTOM w0.127: v2(12.43,0) 11.71,0.72 arc(11.45,0.89) 11.15,0.95 11.03,0.95 arc(10.66,1.03) 10.35,1.24 8.88,2.71 8.88,2.71 v1(8.59,3)
TL_RESET: length 9
  TOP w0.127: C5.2 v1(13.74,10.66) 13.74,9.98 U1.29
  BOTTOM w0.127: v1(13.74,10.66) 13.74,10.7 arc(13.7,10.92) 13.57,11.12 12.93,11.75 arc(12.85,11.87) 12.83,12.01 12.83,12.67 arc(12.77,12.96) 12.6,13.21 11.82,13.99 arc(11.61,14.13) 11.36,14.18 10.17,14.18 arc(9.86,14.24) 9.6,14.42 v2(8.62,15.4)
TL_VBAT: length 13.4
  TOP w0.13: U1.20 16.06,7.63 16.15,7.71
  TOP w0.5: v1(17.94,7.12) 17.7,7.37 v1(17.69,7.37) 17.45,7.6 C7.1 16.15,7.71
  POWER w0.127: v1(17.94,7.12) arc(17.9,7.13) 17.87,7.15 17.72,7.31 arc(17.7,7.33) v1(17.69,7.37)
  POWER w0.5: v2(18.78,15.4) 18.78,13.88 arc(18.85,13.52) 19.05,13.21 arc(19.45,12.62) 19.59,11.93 19.59,7.8 arc(19.37,7.29) 18.86,7.08 18.04,7.08 arc(17.98,7.09) v1(17.94,7.12) 17.7,7.36 arc(17.7,7.36) v1(17.69,7.37)
  BOTTOM w0.5: v1(17.69,7.37) 17.93,7.13 arc(17.93,7.12) v1(17.94,7.12)
TL_XC1: length 3.2
  TOP w0.127: U1.28 13.91,9.61 14.36,10.06 arc(14.48,10.25) 14.53,10.47 14.53,10.77 arc(14.55,10.88) 14.62,10.98 14.68,11.05 14.68,11.4 Y1.3 14.47,11.61 14.45,11.61 C10.1
TL_XC2: length 4.3
  TOP w0.127: 16.17,11.32 Y1.1 ; 16.17,11.32 16.13,11.36 16.13,11.68 C11.2 ; 16.17,11.32 15.56,11.32 arc(15.39,11.28) 15.24,11.19 14.89,10.83 arc(14.83,10.74) 14.81,10.63 14.81,10.42 arc(14.75,10.11) 14.57,9.85 14.12,9.4 U1.27
N20473879: length 1.4
  TOP w0.4: L2.1 10.4,11.93 arc(10.68,11.87) C2.1 11.36,11.27
N20475567: length 3.8
  TOP w0.3: U2.27 23.03,4.3 23.03,4.3
  TOP w0.4: L6.2 22.2,3.82 arc(22.26,3.98) 22.43,4.05 22.43,4.05 arc(22.75,4.11) 23.03,4.3
  TOP w0.5: C19.1 22.11,3.14 L6.2
N20475608: length 2.7
  TOP w0.3: U2.28 23.53,4.63 arc(23.56,4.48) 23.65,4.35
  TOP w0.4: 23.65,4.35 23.75,4.25 arc(24,4.08) 24.29,4.02 24.52,4.02 arc(24.65,3.83) 24.7,3.61 L6.1
N20475681: length 1.9
  TOP w0.3: U2.2 25.02,6.74 arc(25.26,6.69) 25.47,6.55
  TOP w0.5: L5.2 25.94,6.36 arc(25.72,6.5) 25.47,6.55
N20493055: length 1.2
  TOP w0.4: C1.1 C3.1 L2.2
N20502827: length 2.2
  TOP w0.18: C6.1 16.21,9.73 arc(16.14,9.68) 16.05,9.67 15.59,9.66 arc(14.97,9.54) 14.44,9.19 U1.26
N20503268: length 2.1
  TOP w0.18: U1.11 13.75,4.53 arc(13.74,4.51) 13.73,4.49
  TOP w0.33: 13.73,4.49 C12.2 ; 13.73,4.49 13.73,4.84 ; 13.73,4.49 arc(13.76,4.62) 13.83,4.73
N20503276: length 2.7
  TOP w0.18: U1.15 14.76,5.91 15.23,5.44 arc(15.36,5.36) 15.52,5.33 15.76,5.33
  TOP w0.33: C13.1 16.2,5.51 arc(16,5.37) 15.76,5.33
N20503917: length 4.2
  TOP w0.18: U1.13 14.55,5.11 arc(14.65,4.97) 14.68,4.8
  TOP w0.4: 14.68,3.37 L3.2 14.38,3.37 14.38,4.5 14.68,4.8 14.68,3.37

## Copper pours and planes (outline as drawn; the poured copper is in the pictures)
GND on TOP (solid shape): 6.08,14.13 0.77,14.13 0.77,12.13 6.37,12.13 6.37,11.73 0.77,11.73 0.77,10.21 3.87,10.21 3.87,7.89 0.77,7.89 0.77,6.37 3.87,6.37 3.87,4.05 0.77,4.05 0.77,2.53 3.87,2.53 3.87,0.21 0.37,0.21 0.37,0.61 3.47,0.61 3.47,2.13 0.37,2.13 0.37,4.45 3.47,4.45 3.47,5.97 0.37,5.97 0.37,8.29 3.47,8.29 3.47,9.81 0.37,9.81 0.37,15.03 6.08,15.03
GND on TOP: 6.85,14.49 28.12,14.49 28.12,0.91 6.85,0.91 6.85,11.45 10.56,11.45 11.96,10.05 11.96,9.92 12.13,9.92 12.25,10.04 10.69,11.6 10.38,11.6 10.35,11.57 10.35,11.73 7.97,11.73 8.04,11.8 8.04,12.08 7.99,12.13 10.35,12.13 10.35,12.23 12.8,9.77 13,9.77 13,10.31 10.9,12.41 6.85,12.41 ; 16 cut-outs
GND on BOTTOM: 28.12,0.91 28.12,14.49 6.85,14.49 6.85,0.91 ; 1 cut-out
GND on GND: 28.12,0.91 28.12,14.49 6.85,14.49 6.85,0.91
GND on POWER: 28.12,0.91 28.12,14.49 6.85,14.49 6.85,0.91 ; 2 cut-outs

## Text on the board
Ref Des/Silkscreen Bottom: ML3219D-VENUS-M1-PA11-V01
User.Comments: #4 | #3 | #1 | #2 | TOP | #5
User.6: FIGURE | FINISHED_SIZE | 0.2 | 0.55 | DRILL CHART: TOP to BOTTOM | ALL UNITS ARE IN MILLIMETERS | PLATED | QTY | 286 | 45
